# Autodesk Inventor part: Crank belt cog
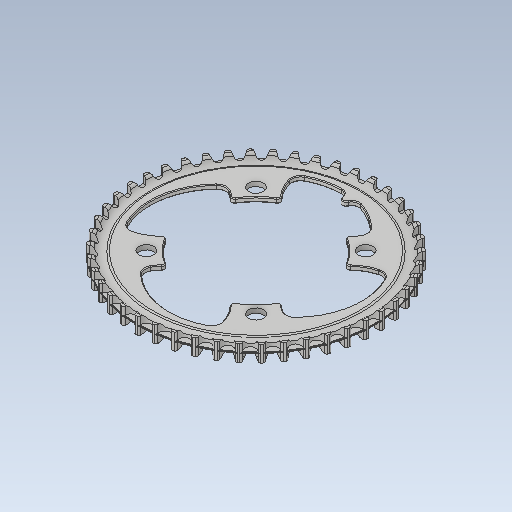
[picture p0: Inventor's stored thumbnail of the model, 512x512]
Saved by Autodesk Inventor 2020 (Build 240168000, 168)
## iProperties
Created: 2017-10
Part Number: Crank belt cog
Material: Ogólny
Document SubType Name: Modeling
Designer: Tomasz
Density: 1 g/cm^3
Appearance: Domyślna
Sending System: SolidWorks 2017
Last Author: Tomasz
Last Saved: 2017-10-01
Author: Tomasz
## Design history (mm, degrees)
feature "Crank belt cog.ipt"
node "Bryła1"
